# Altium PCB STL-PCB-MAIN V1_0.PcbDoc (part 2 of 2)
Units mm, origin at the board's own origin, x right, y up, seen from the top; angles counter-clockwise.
Board outline 48 x 35.2 mm, 4 copper layers (Top Layer, Int1 (GND), Int4 (PWR), Bottom Layer), stack 0.969 mm thick; 79 components, 63 nets, 420 pads, 232 vias.
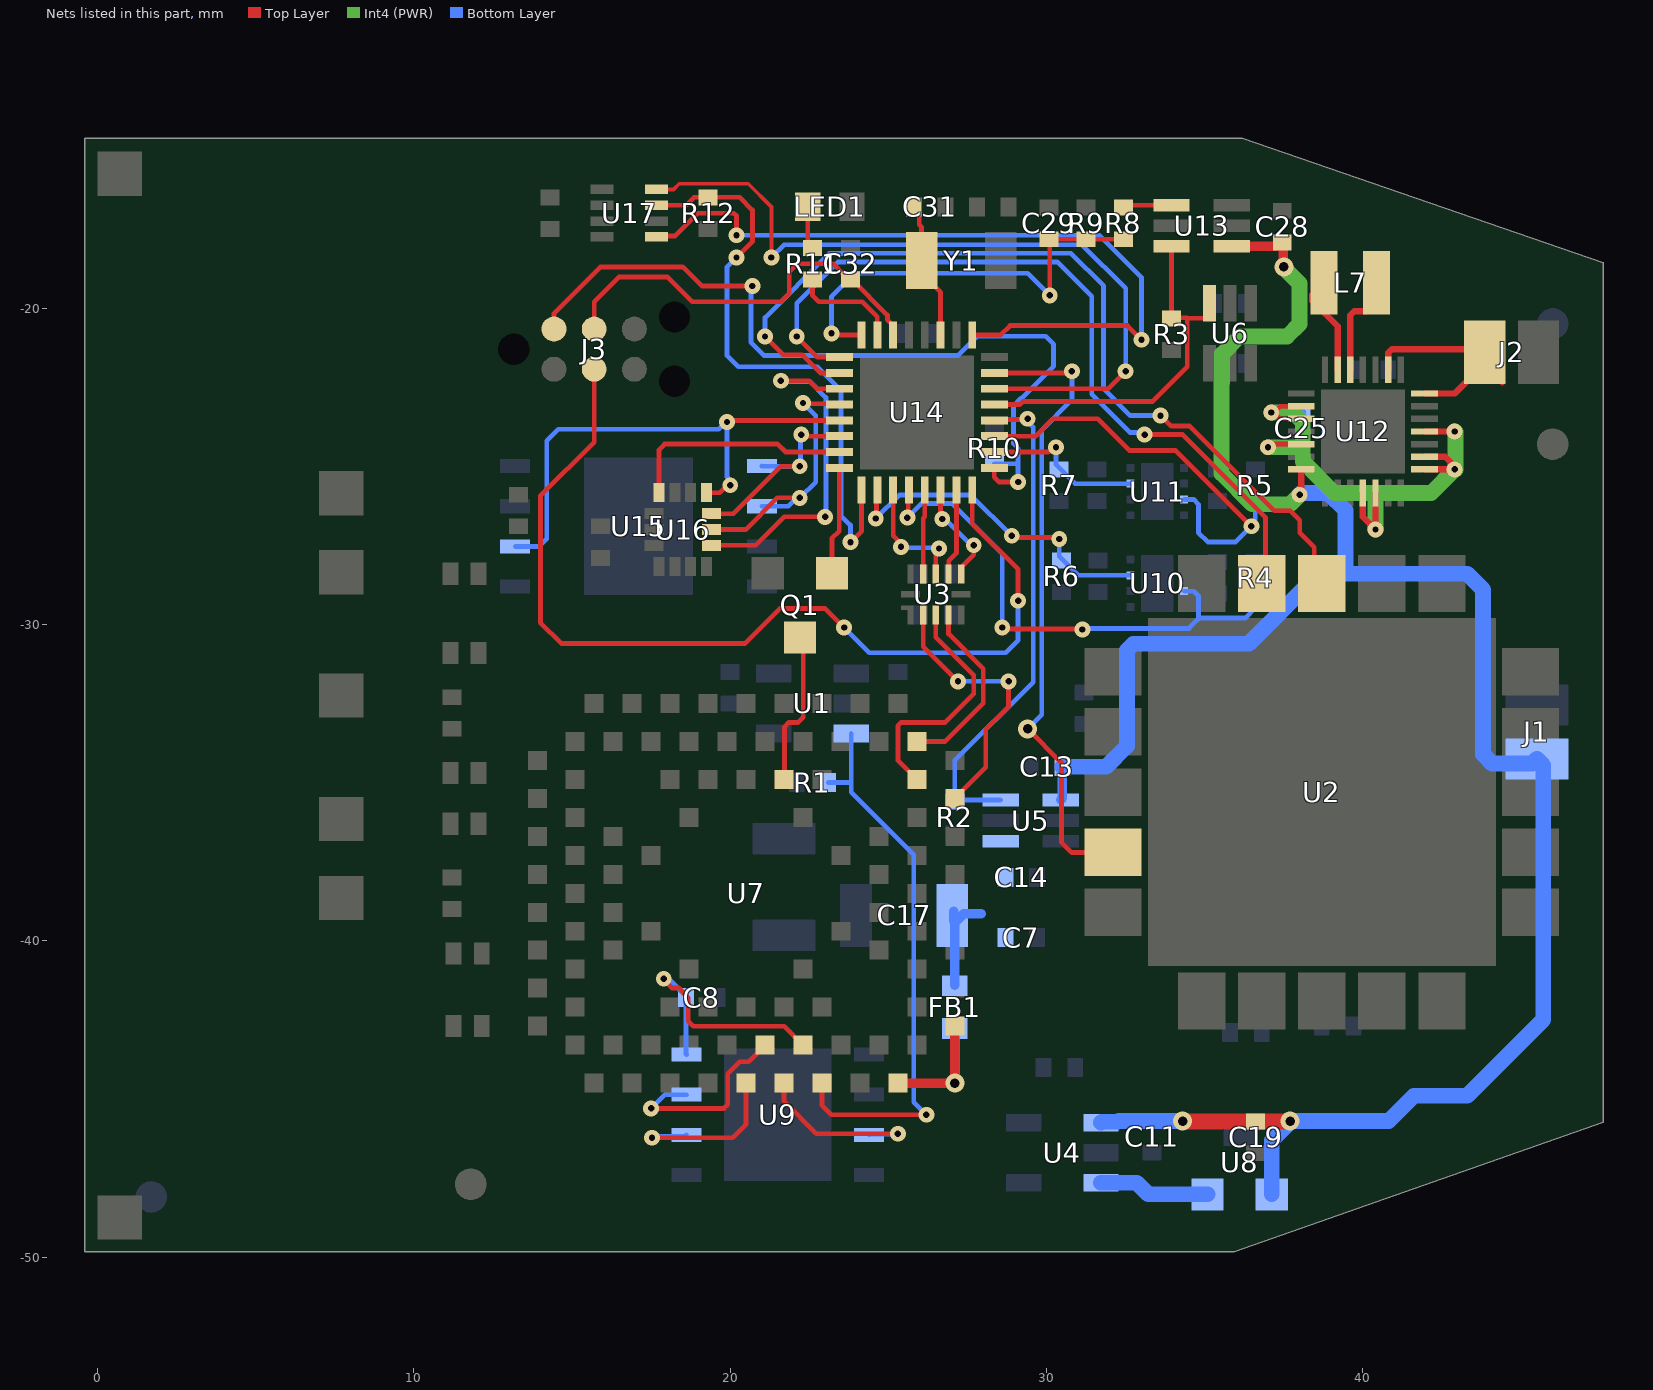
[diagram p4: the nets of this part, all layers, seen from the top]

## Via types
v1: diameter 0.6, hole 0.3, Top Layer to Bottom Layer, 120 vias
v2: diameter 0.5, hole 0.2, Top Layer to Bottom Layer, 112 vias

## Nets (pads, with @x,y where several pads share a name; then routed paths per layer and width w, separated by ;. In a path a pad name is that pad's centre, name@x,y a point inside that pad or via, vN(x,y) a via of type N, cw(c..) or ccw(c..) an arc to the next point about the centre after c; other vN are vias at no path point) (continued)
NetC31_1: C31.1 U14.3 Y1.1 | length 4.4
  Top Layer w0.15: C31.1@25.8,-16.8 25.975,-16.975 25.975,-17.363 26.05,-17.438 Y1.1@26.05,-18.5 26.05,-18.9 26.65,-19.5 U14.3@26.65,-20.85
NetFB1_1: FB1.1 U7.AA3 U7.W1 | length 5.3
  Top Layer w0.3: U7.W1@25.3,-44.5 v1(27.1,-44.5) U7.AA3@27.1,-42.7
  Bottom Layer w0.3: v1(27.1,-44.5) FB1.1@27.1,-42.775
NetJ2_1: J2.1 U12.2 U12.28 | length 7.6
  Top Layer w0.2: U12.2@40.8,-21.95 40.8,-21.417 40.917,-21.3 43.75,-21.3 J2.1@43.85,-21.4 43.85,-21.75 42.9,-22.7 U12.28@41.95,-22.7 ; J2.1@43.583,-21.4 43.892,-21.708 43.892,-21.842 J2.1@44.4,-22.35
NetL7_1: L7.1 U12.6 | length 3.2
  Top Layer w0.2: L7.1@38.775,-19.2 38.4,-19.575 38.4,-19.775 39.2,-20.575 U12.6@39.2,-21.95
NetL7_2: L7.2 U12.5 | length 3.3
  Top Layer w0.2: U12.5@39.6,-21.95 39.6,-20.225 39.725,-20.1 40.1,-20.1 40.425,-19.775 L7.2@40.425,-19.2
NetLED1_2: LED1.2 R11.1 | length 1.4
  Top Layer w0.15: LED1.2@22.45,-16.8 22.45,-17.95 R11.1@22.6,-18.1
NetQ1_1: Q1.1 U14.16 | length 3.4
  Top Layer w0.15: Q1.1@23.216,-28.384 23.216,-27.284 23.45,-27.05 U14.16@23.45,-25.05
NetQ1_3: Q1.3 U7.N16 | length 5
  Top Layer w0.15: U7.N16@21.7,-34.9 21.718,-34.882 21.718,-33.238 21.856,-33.1 22.144,-33.1 22.312,-32.932 22.312,-30.528 Q1.3@22.2,-30.416
NetR1_2: R1.2 U1.3 U7.R1 | length 17.9
  Top Layer w0.15: U7.R1@22.9,-44.5 22.9,-45.2 23.2,-45.5 v2(26.2,-45.5)
  Bottom Layer w0.15: R1.2@23.1,-35 23.822,-35 ; U1.3@23.822,-33.45 23.822,-35 ; v2(26.2,-45.5) 25.8,-45.1 25.8,-37.285 23.822,-35.307 23.822,-35
NetR2_2: R2.2 U5.3 U14.28 | length 15.7
  Top Layer w0.15: U14.28@28.35,-23.55 28.375,-23.525 29.375,-23.525 v2(29.4,-23.5)
  Bottom Layer w0.15: U5.3@28.55,-35.55 27.15,-35.55 R2.2@27.1,-35.6 27.1,-34.3 29.575,-31.825 29.575,-23.763 29.4,-23.588 v2(29.4,-23.5)
NetR4_1: R4.1 U10.3 U14.20 | length 17.1
  Top Layer w0.15: v2(25.6,-26.625) 25.625,-26.6 25.625,-25.775 U14.20@25.65,-25.75 ; v2(28.6,-30.1) 28.645,-30.145 31.118,-30.145 v2(31.132,-30.159)
  Bottom Layer w0.15: v2(25.6,-26.625) 26.044,-26.181 27.018,-26.181 28.6,-27.763 v2(28.6,-30.1) ; v2(31.132,-30.159) 31.163,-30.128 34.5,-30.128 34.8,-29.828 34.8,-29.1 34.65,-28.95 U10.3@34.35,-28.95 ; 34.8,-29.8 36.273,-29.8 36.6,-29.473 R4.1@36.6,-29.025
NetR5_1: R5.1 U11.3 U14.27 | length 14
  Top Layer w0.15: U14.27@28.35,-24.05 29.65,-24.05 30.2,-23.5 31.615,-23.5 32.615,-24.5 34.075,-24.5 v2(36.475,-26.9)
  Bottom Layer w0.15: U11.3@34.35,-26.05 34.65,-26.05 34.8,-26.2 34.8,-27.1 35.095,-27.395 35.98,-27.395 v2(36.475,-26.9) 36.475,-26.805 36.6,-26.68 R5.1@36.6,-26.1
NetR6_2: R6.2 U10.7 U14.18 | length 10.7
  Top Layer w0.15: v2(24.6,-26.65) 24.625,-26.625 24.625,-25.775 U14.18@24.65,-25.75 ; v2(28.9,-27.2) 28.95,-27.25 30.35,-27.25 v2(30.4,-27.3)
  Bottom Layer w0.15: v2(24.6,-26.65) 25.339,-25.911 27.611,-25.911 v2(28.9,-27.2) ; v2(30.4,-27.3) 30.4,-27.85 31,-28.45 U10.7@32.65,-28.45
NetR7_2: R7.2 U11.7 U14.26 | length 5.2
  Top Layer w0.15: U14.26@28.35,-24.55 30.055,-24.55 30.205,-24.4 v2(30.3,-24.4)
  Bottom Layer w0.15: v2(30.3,-24.4) 30.3,-24.95 30.9,-25.55 U11.7@32.65,-25.55
NetR8_2: R8.2 U13.1 | length 1.6
  Top Layer w0.15: R8.2@32.425,-16.825 32.5,-16.75 U13.1@33.95,-16.75
NetR11_2: R11.2 U14.7 | length 3.4
  Top Layer w0.15: R11.2@22.6,-19.1 22.6,-19.6 22.8,-19.8 24.168,-19.8 24.65,-20.282 U14.7@24.65,-20.85
NetR12_1: R12.1 U14.17 U17.7 | length 19
  Top Layer w0.15: U17.7@17.67,-16.75 18.606,-16.75 18.856,-16.5 R12.1@19.3,-16.5 20.299,-16.5 20.7,-16.901 20.7,-17.9 v2(20.2,-18.4) ; v2(23.8,-27.4) 24.15,-27.05 U14.17@24.15,-25.75
  Bottom Layer w0.15: v2(20.2,-18.4) 19.9,-18.7 19.9,-21.5 20.255,-21.855 22.755,-21.855 23.5,-22.6 23.5,-26.561 23.8,-26.861 v2(23.8,-27.4)
NetU2_13: U2.13 U14.10 | length 28.9
  Top Layer w0.15: v2(21.1,-20.9) 21.675,-21.475 22.275,-21.475 22.85,-22.05 U14.10@23.45,-22.05 ; v2(33.6,-23.4) 33.612,-23.4 33.942,-23.73 34.527,-23.73 37.202,-26.405 37.705,-26.405 38.005,-26.705 38.005,-27.105 38.463,-27.563 38.463,-28.463 U2.13@38.7,-28.7
  Bottom Layer w0.15: v2(21.1,-20.9) 21.1,-20.3 23.13,-18.27 30.77,-18.27 31.8,-19.3 31.8,-22.556 32.644,-23.4 v2(33.6,-23.4)
NetU2_14: U2.14 U14.9 | length 25.3
  Top Layer w0.15: v2(22.1,-20.9) 22.75,-21.55 U14.9@23.45,-21.55 ; v2(33.1,-24) 34.3,-24 36.92,-26.62 36.92,-28.58 U2.14@36.8,-28.7
  Bottom Layer w0.15: v2(22.1,-20.9) 22.1,-19.85 23.41,-18.54 30.34,-18.54 31.428,-19.628 31.428,-22.728 32.633,-23.933 33.033,-23.933 v2(33.1,-24)
NetU2_19: U2.19 U14.31 | length 20.2
  Top Layer w0.15: U14.31@28.35,-22.05 30.75,-22.05 v2(30.8,-22) ; v1(29.4,-33.3) 30.468,-34.368 30.468,-36.886 30.794,-37.212 32.088,-37.212 U2.19@32.1,-37.2
  Bottom Layer w0.15: v1(29.4,-33.3) 29.845,-32.855 29.845,-23.855 30.8,-22.9 v2(30.8,-22)
NetU3_7: U3.7 U14.22 | length 3.3
  Top Layer w0.15: U14.22@26.65,-25.75 26.65,-26.611 v2(26.705,-26.666) ; U3.7@27.3,-28.4 27.3,-28.2 27.7,-27.8 v2(27.7,-27.5)
  Bottom Layer w0.15: v2(26.705,-26.666) 26.786,-26.666 27.619,-27.5 v2(27.7,-27.5)
NetU3_8: U3.8 U14.23 | length 2.8
  Top Layer w0.15: U3.8@26.9,-28.4 26.909,-28.391 26.909,-27.991 27.15,-27.75 U14.23@27.15,-25.75
NetU3_9: U3.9 U14.19 | length 4
  Top Layer w0.15: U14.19@25.15,-25.75 25.15,-27.205 25.4,-27.455 v2(25.4,-27.55) ; U3.9@26.5,-28.4 26.5,-27.795 26.6,-27.695 v2(26.6,-27.6)
  Bottom Layer w0.15: v2(25.4,-27.55) 25.425,-27.575 26.575,-27.575 v2(26.6,-27.6)
NetU3_10: U3.10 U14.21 | length 2.7
  Top Layer w0.15: U3.10@26.1,-28.4 26.1,-26.65 26.15,-26.6 U14.21@26.15,-25.75
NetU4_3: U4.3 U8.2 | length 3.5
  Bottom Layer w0.5: U4.3@31.722,-47.65 32.85,-47.65 33.216,-48.016 U8.2@35.084,-48.016
NetU14_1: U14.1 U17.5 | length 24.5
  Top Layer w0.15: U17.5@17.67,-17.75 17.701,-17.719 18.255,-17.719 18.974,-17 20.112,-17 20.2,-17.088 v2(20.2,-17.7) ; U14.1@27.65,-20.85 28.55,-20.85 28.845,-20.555 32.555,-20.555 v2(33,-21)
  Bottom Layer w0.15: v2(20.2,-17.7) 31.671,-17.7 33,-19.029 v2(33,-21)
NetU14_11: U14.11 U16.12 | length 11.3
  Top Layer w0.15: U16.12@19.412,-27.5 20.81,-27.5 21.71,-26.6 v2(23,-26.6) ; v2(21.6,-22.3) 22.494,-22.3 22.744,-22.55 U14.11@23.45,-22.55
  Bottom Layer w0.15: v2(21.6,-22.3) 21.621,-22.321 22.515,-22.321 23.025,-22.831 23.025,-26.575 v2(23,-26.6)
NetU14_15: U14.15 U16.4 | length 7.2
  Top Layer w0.15: U16.4@17.75,-25.837 17.75,-24.476 17.926,-24.3 21.5,-24.3 21.75,-24.55 U14.15@23.45,-24.55
NetU14_30: U14.30 U17.8 | length 24.5
  Top Layer w0.12: U17.8@17.67,-16.25 18.208,-16.25 18.388,-16.07 20.57,-16.07 21.3,-16.8 v2(21.3,-18.4)
  Top Layer w0.15: U14.30@28.35,-22.55 31.95,-22.55 v2(32.5,-22)
  Bottom Layer w0.15: v2(21.3,-18.4) 21.7,-18 31.12,-18 32.5,-19.38 v2(32.5,-22)
NRST: C32.1 J3.4 U14.6 | length 13.3
  Top Layer w0.15: J3.4@15.7,-20.865 15.7,-19.8 16.48,-19.02 18.02,-19.02 18.8,-19.8 21.6,-19.8 21.862,-19.538 21.862,-18.85 22.112,-18.6 23.25,-18.6 23.75,-19.1 C32.1@23.8,-19.1 23.85,-19.1 24.97,-20.22 24.97,-20.37 25.15,-20.55 U14.6@25.15,-20.85
ON_OFF: R3.2 U6.3 U13.3 U14.29 | length 12
  Top Layer w0.15: U14.29@28.35,-23.05 29.152,-23.05 29.248,-22.955 33.345,-22.955 34.445,-21.855 34.445,-20.305 R3.2@33.95,-20.305 ; R3.2@33.95,-20.325 R3.2@33.95,-20.305 ; U13.3@33.95,-18.05 R3.2@33.95,-20.305 ; 34.445,-20.325 35.025,-20.325 35.15,-20.2 U6.3@35.15,-19.85
RTS1V8: U3.4 U7.Y18 | length 5.9
  Top Layer w0.15: U7.Y18@25.9,-33.7 26.8,-33.7 28,-32.5 28,-31.4 26.9,-30.3 U3.4@26.9,-29.7
RX1V8: U3.2 U7.AA15 | length 8.6
  Top Layer w0.15: U3.2@26.1,-29.7 26.1,-30.7 v2(27.2,-31.8) ; U7.AA15@27.1,-35.5 28.079,-34.521 28.079,-33.321 28.8,-32.6 v2(28.8,-31.8)
  Bottom Layer w0.15: v2(27.2,-31.8) v2(28.8,-31.8)
SIMCLK: U7.L1 U9.6 | length 5.6
  Top Layer w0.15: v2(17.525,-46.225) 20.075,-46.225 20.5,-45.8 U7.L1@20.5,-44.5
  Bottom Layer w0.15: v2(17.525,-46.225) 17.57,-46.18 18.57,-46.18 U9.6@18.615,-46.135
SIMDAT: U7.N1 U9.3 | length 5.5
  Top Layer w0.15: U7.N1@21.7,-44.5 21.7,-45.075 22.725,-46.1 v2(25.3,-46.1)
  Bottom Layer w0.15: U9.3@24.385,-46.135 24.403,-46.117 25.282,-46.117 v2(25.3,-46.1)
SIMRST: U7.M2 U9.7 | length 6.3
  Top Layer w0.15: v2(17.5,-45.3) 19.8,-45.3 19.922,-45.178 19.922,-44.202 20.302,-43.822 20.578,-43.822 U7.M2@21.1,-43.3
  Bottom Layer w0.15: v2(17.5,-45.3) 17.935,-44.865 U9.7@18.615,-44.865
SIMVCC: C8.2 U7.P2 U9.8 | length 8.5
  Top Layer w0.15: v2(17.9,-41.2) 17.9,-41.239 18.154,-41.493 18.369,-41.493 18.675,-41.799 18.675,-42.543 18.832,-42.7 21.7,-42.7 U7.P2@22.3,-43.3
  Bottom Layer w0.15: v2(17.9,-41.2) 17.967,-41.267 18.117,-41.267 18.6,-41.75 C8.2@18.6,-41.8 18.6,-43.58 U9.8@18.615,-43.595
SPI_MISO: U14.13 U15.2 U16.1 | length 16.6
  Top Layer w0.15: U16.1@19.25,-25.837 19.668,-25.837 19.905,-25.6 v2(20,-25.6) ; v2(19.9,-23.6) 19.945,-23.555 23.445,-23.555 U14.13@23.45,-23.55
  Bottom Layer w0.15: U15.2@13.2,-27.535 13.965,-27.535 14.2,-27.3 14.2,-24.2 14.571,-23.829 19.637,-23.829 19.867,-23.6 v2(19.9,-23.6) 19.9,-25.337 19.933,-25.37 19.933,-25.533 v2(20,-25.6)
SPI_MOSI: U14.14 U15.5 U16.14 | length 6.9
  Top Layer w0.15: U16.14@19.412,-26.5 20.102,-26.5 21.602,-25 v2(22.2,-25) ; v2(22.245,-24) 22.295,-24.05 U14.14@23.45,-24.05
  Bottom Layer w0.15: U15.5@21,-24.995 21.005,-25 v2(22.2,-25) 22.223,-24.977 22.223,-24.068 22.2,-24.045 v2(22.245,-24)
SPI_SCK: U14.12 U15.6 U16.13 | length 9.1
  Top Layer w0.15: U16.13@19.412,-27 20.49,-27 21.49,-26 v2(22.2,-26) ; v2(22.3,-23) 22.325,-23.025 23.425,-23.025 U14.12@23.45,-23.05
  Bottom Layer w0.15: U15.6@21,-26.265 21.84,-26.265 22.105,-26 v2(22.2,-26) 22.7,-25.5 22.7,-23.4 v2(22.3,-23)
SWDCLK: J3.2 R10.1 U14.25 | length 26.6
  Top Layer w0.15: J3.2@14.43,-20.865 14.43,-20.17 15.9,-18.7 18.5,-18.7 19.1,-19.3 v2(20.7,-19.3) ; U14.25@28.35,-25.05 28.35,-25.35 28.5,-25.5 v2(29.1,-25.5)
  Bottom Layer w0.15: v2(20.7,-19.3) 20.655,-19.345 20.655,-21.084 21.071,-21.5 27.2,-21.5 27.812,-20.887 29.968,-20.887 30.222,-21.142 30.222,-21.837 29.209,-22.85 29.185,-22.85 28.955,-23.081 28.955,-24.288 29.1,-24.433 29.1,-24.966 ; R10.1@28.35,-24.925 29.059,-24.925 29.1,-24.966 ; v2(29.1,-25.5) 29.1,-24.966
SWDIO: J3.3 U14.24 | length 30.4
  Top Layer w0.15: J3.3@15.7,-22.135 15.7,-24.236 14,-25.936 14,-29.945 14.655,-30.6 20.471,-30.6 21.571,-29.5 23,-29.5 v2(23.6,-30.1) ; U14.24@27.65,-25.75 27.65,-26.813 29.1,-28.263 v2(29.1,-29.25)
  Bottom Layer w0.15: v2(23.6,-30.1) 24.395,-30.895 28.705,-30.895 29.1,-30.5 v2(29.1,-29.25)
TX1V8: U3.3 U7.Y16 | length 7.8
  Top Layer w0.15: U7.Y16@25.9,-34.9 25.3,-34.3 25.3,-33.2 25.4,-33.1 26.8,-33.1 27.7,-32.2 27.7,-31.6 26.5,-30.4 ; 26.5,-30.399 U3.3@26.5,-29.7
VBAT: C11.2 C13.2 C19.2 C28.2 J1.1 U4.1 U5.4 U8.1 U12.14 U13.4 | length 70.6
  Top Layer w0.2: v2(38,-25.9) 38.05,-25.85 U12.14@38.05,-25.1
  Top Layer w0.3: U13.4@35.85,-18.05 C28.2@37.275,-18.05 ; C28.2@37.45,-17.925 37.475,-17.95 37.475,-18.675 v1(37.5,-18.7)
  Top Layer w0.5: v1(34.3,-45.7) 34.318,-45.718 C19.2@36.608,-45.718 37.682,-45.718 v1(37.7,-45.7)
  Int4 (PWR) w0.5: v1(37.5,-18.7) 37.5,-18.727 38,-19.227 38,-20.5 37.6,-20.9 36.1,-20.9 35.55,-21.45 35.55,-22.354 35.53,-22.374 35.53,-25.23 36.5,-26.2 37.7,-26.2 v2(38,-25.9)
  Bottom Layer w0.3: U5.4@30.45,-35.55 30.5,-35.5 C13.2@30.5,-34.5
  Bottom Layer w0.5: C13.2@30.5,-34.5 31.886,-34.5 32.542,-33.844 32.542,-30.82 32.75,-30.612 36.39,-30.612 38.603,-28.4 39.45,-28.4 ; U4.1@31.722,-45.75 31.751,-45.721 32.259,-45.721 32.279,-45.7 C11.2@33.329,-45.7 v1(34.3,-45.7) ; U8.1@37.116,-48.016 37.116,-46.311 37.7,-45.727 v1(37.7,-45.7) 40.814,-45.7 41.614,-44.9 43.3,-44.9 45.7,-42.5 45.7,-34.45 J1.1@45.5,-34.25 45.35,-34.4 44.093,-34.4 43.8,-34.107 43.8,-28.906 43.294,-28.4 39.45,-28.4 ; v2(38,-25.9) 38.05,-25.85 38.9,-25.85 39.45,-26.4 39.45,-28.4
VBAT_MEAS: C29.2 R8.1 R9.2 U14.8 | length 13.8
  Top Layer w0.15: v2(23.2,-20.8) 23.25,-20.85 U14.8@24.15,-20.85 ; v2(30.1,-19.6) 30.1,-17.85 C29.2@30.075,-17.825 R9.2@31.25,-17.825 R8.1@32.425,-17.825
  Bottom Layer w0.15: v2(23.2,-20.8) 23.2,-19.65 23.95,-18.9 29.4,-18.9 v2(30.1,-19.6)
VINT: C25.2 U12.9 U12.10 U12.12 U12.18 U12.19 U12.22 U12.23 U12.25 | length 20.7
  Top Layer w0.15: v2(37.1,-23.3) v2@37.195,-23.3 ; v2@37.195,-24.3 U12.12@38.05,-24.3 ; U12.10@38.05,-23.5 37.395,-23.5 v2@37.195,-23.3 ; U12.9@38.05,-23.1 37.395,-23.1 v2@37.195,-23.3
  Top Layer w0.2: U12.18@40,-25.85 40,-26.6 v2(40.4,-27) U12.19@40.4,-25.85 ; U12.22@41.95,-25.1 v2(42.9,-25.1) 42.843,-25.043 42.843,-24.943 42.6,-24.7 U12.23@41.95,-24.7 ; U12.25@41.95,-23.9 v2(42.9,-23.9)
  Int4 (PWR) w0.5: v2(37,-24.4) 38.1,-24.4 ; v2(37.1,-23.3) 37.8,-23.3 38.1,-23.6 38.1,-24.4 ; v2(40.4,-27) 40.4,-25.85 ; v2(42.9,-25.1) 42.15,-25.85 40.4,-25.85 ; v2(42.9,-23.9) 42.922,-23.922 v2@42.922,-25.1 ; 38.1,-24.4 38.1,-24.848 39.102,-25.85 40.4,-25.85
  Bottom Layer w0.3: v2(37.1,-23.3) C25.2@38.05,-23.3
VLTE: C7.2 C14.2 C17.2 FB1.2 U5.1 | length 3.3
  Bottom Layer w0.3: C17.2@27.064,-39.069 27.064,-39.388 27.076,-39.4 C17.2@27.1,-39.424 ; FB1.2@27.1,-41.4 C17.2@27.1,-39.424 ; 27.938,-39.15 27.374,-39.15 C17.2@27.1,-39.424
pads on no net: ANT1.1 ANT1.2 ANT1.6 ANT1.7 J3.5 J3.7 J3.8 J3.9 U1.4 U2.7 U2.8 U2.9 U2.12 U2.18 U4.4 U5.6 U6.6 U7.A11 U7.A15 U7.AA5 U7.AA7 U7.AA9 U7.AA11 U7.AA13 U7.B2 U7.B8 U7.B18 U7.C1 U7.D2 U7.D7 U7.D9 U7.D11 U7.D13 U7.E1 U7.E19 U7.F2 U7.G1 U7.G4 U7.G16 U7.H2 U7.H18 U7.J1 U7.J4 U7.J16 U7.K2 U7.L4 U7.L16 U7.L19 U7.P18 U7.R4 U7.R16 U7.R19 U7.T2 U7.T18 U7.U19 U7.V7 U7.V9 U7.V11 U7.V13 U7.V18 U7.Y6 U7.Y8 U7.Y10 U7.Y12 U7.Y14 U9.2 U9.4 U9.5 U10.4 U11.4 U12.1 U12.15 U12.16 U12.17 U12.26 U13.6 U16.9 U16.10 U16.11 U17.3 U17.6

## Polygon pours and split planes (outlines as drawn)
GND on Int1 (GND) "NONET_L-01_P-001" (solid, remove dead copper, pour order 0): 12,-12.9 52.5,-12.9 52.5,-49.2 49.9,-51.8 49.8,-51.7 12,-51.7
GND on Int4 (PWR) "NONET_L-01_P-001" (solid, remove dead copper, pour order 1): 12.4,-12.7 51.9,-12.7 51.9,-47 44.6,-54.3 42.8,-52.5 12.4,-52.5
GND on Top Layer "NONET_L-01_P-001" (solid, remove dead copper, pour order 2): 12,-11.4 50,-11.4 52.9,-14.3 52.7,-14.5 52.7,-49 48.6,-53.1 12,-53.1
GND on Bottom Layer "NONET_L-01_P-001" (solid, remove dead copper, pour order 3): 12.1,-11.7 46.5,-11.7 52.1,-17.3 52.1,-44.2 44.7,-51.6 12.1,-51.6

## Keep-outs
Top Layer:
  circle w0.1: c11.8,-47.7 r1.204
  circle w0.1: c46,-24.3 r1.105
  region: 11.577,-14.625 11.577,-15.7 47.9,-15.7 47.9,-14.625
  region: 8.7,-48.7 8.7,-49.75 49.2,-49.75 49.2,-48.7
Bottom Layer:
  circle w0.1: c1.7,-48.1 r1.105
  circle w0.1: c46,-20.5 r1.105
Keep-Out Layer:
  lines w1: -0.4,-49.825 -0.4,-14.625 36.188,-14.625 47.719,-18.603 47.719,-45.696 35.933,-49.825 -0.4,-49.825

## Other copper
Top Layer:
  rectangle net +1V8: 24.125,-30.8 25.375,-28.95
  rectangle net GND: 44.9,-22.8 46.7,-20
  rectangle net NetJ2_1: 42.667,-22.8 44.5,-20
  pour cut-out: 13.407,-20.471 18.148,-20.471 18.148,-22.529 13.407,-22.529
  pour cut-out: 12.594,-26.835 12.594,-43.4 10.5,-43.4 10.5,-26.782
  text "FACE GRAVURE REFERENCE" at 17.543,-128.273 h1.78
Int1 (GND):
  text "FACE GRAVURE INTERNE 1" at 14.693,-128.523 h1.78
Int4 (PWR):
  text "FACE GRAVURE INTERNE 4" at 59.443,-128.423 h1.78
Bottom Layer:
  rectangle net VBAT: 44.5,-36.3 46.8,-33.6
  rectangle net GND: 44.5,-33.2 46.8,-30.5
  rectangle net VLTE: 26.676,-40.2 28.95,-38.2
  region net VLTE: 28.999,-36.65 27.975,-36.65 27.975,-39.312 28.999,-39.312
  pour cut-out: 10.553,-26.835 12.594,-26.835 12.594,-43.4 10.525,-43.4 10.525,-26.807
  text "FACE GRAVURE VERSO" at 59.443,-128.423 h1.78

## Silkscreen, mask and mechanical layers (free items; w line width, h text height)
Top Overlay:
  text "PV" at 43.1,-19.8 h1
  text "GND" at 44.7,-19.788 h1
  text "STL-PCB-MAIN V1_0" at 13.784,-49.36 h1.5
  text "FACE SERIGRAPHIE REFERENCE" at 18.243,-128.073 h1.78
Bottom Overlay:
  text "STL-PCB-MAIN V1_0" at 35.3,-16.735 h1.5
  text "GND" at 46.2,-31.288 h1
  text "+VBAT" at 46.6,-36.3 h1
  text "FACE SERIGRAPHIE VERSO" at 62.043,-128.223 h1.78
Top Paste:
  text "FACE BRASAGE REFERENCE" at 14.943,-128.023 h1.78
Bottom Paste:
  text "FACE BRASAGE VERSO" at 59.043,-128.423 h1.78
Top Solder:
  text "FACE VERNIS EPARGNE REFERENCE" at 7.643,-128.123 h1.78
Bottom Solder:
  text "FACE VERNIS EPARGNE VERSO" at 64.943,-128.323 h1.78
Top Mechanical 1/Mechanical 2:
  circle w0.013: c37.362,18.974 r0.495
  circle w0.013: c37.362,21.006 r0.495
  circle w0.013: c62.447,8.447 r0.5
  circle w0.013: c67.547,13.547 r0.5
  circle w0.013: c57.997,10.997 r1
  circle w0.013: c64.997,4.997 r0.375
  circle w0.013: c62.447,13.547 r0.5
  circle w0.013: c67.547,8.447 r0.5
  circle w0.013: c34.797,10.997 r0.5
  circle w0.013: c42.442,19.99 r0.495
  circle w0.013: c32.297,10.997 r0.4
  circle w0.013: c71.997,10.997 r1
  circle w0.013: c67.547,8.447 r0.5
  circle w0.013: c67.547,8.447 r0.5
  circle w0.013: c37.362,21.006 r0.495
  circle w0.013: c37.362,18.974 r0.495
  circle w0.013: c42.442,19.99 r0.495
  circle w0.013: c64.997,4.997 r0.375
  circle w0.013: c62.447,8.447 r0.5
  circle w0.013: c62.447,8.447 r0.5
  circle w0.013: c57.997,10.997 r1
  circle w0.013: c57.997,10.997 r1
  circle w0.013: c62.447,13.547 r0.5
  circle w0.013: c62.447,13.547 r0.5
  circle w0.013: c67.547,13.547 r0.5
  circle w0.013: c67.547,13.547 r0.5
  lines w0.013: 0,0 0,36.322 ; 0,0 0,36.322 ; 0,0 0,36.322 ; 0,36.322 10.597,36.322 ; 0,36.322 10.597,36.322 ; 0,36.322 10.597,36.322 ; 50.372,21.997 cw(c49.997,21.997) 49.622,21.997 ccw(c49.997,21.997) 50.372,21.997 ; 50.372,21.997 74.997,21.997 ; 50.372,21.997 74.997,21.997 ; 70.988,10.997 71.023,10.736 ; 70.988,10.997 71.023,11.258 ; 70.988,10.997 71.023,10.736 ; 70.988,10.997 71.023,11.258 ; 71.023,10.736 71.124,10.493 ; 71.023,10.736 71.124,10.493 ; 71.023,11.258 71.124,11.501 ; 71.023,11.258 71.124,11.501 ; 71.124,10.493 71.284,10.284 ; 71.124,10.493 71.284,10.284 ; 71.124,11.501 71.284,11.71 ; 71.124,11.501 71.284,11.71 ; 71.284,10.284 71.493,10.123 ; 71.284,10.284 71.493,10.123 ; 71.284,11.71 71.493,11.87 ; 71.284,11.71 71.493,11.87 ; 71.493,10.123 71.736,10.023 ; 71.493,10.123 71.736,10.023 ; 71.493,11.87 71.736,11.971 ; 71.493,11.87 71.736,11.971 ; 71.736,10.023 71.997,9.988 ; 71.736,10.023 71.997,9.988 ; 71.736,11.971 71.997,12.006 ; 71.736,11.971 71.997,12.006 ; 71.997,9.988 72.258,10.023 ; 71.997,9.988 72.258,10.023 ; 71.997,12.006 72.258,11.971 ; 71.997,12.006 72.258,11.971 ; 72.258,10.023 72.501,10.123 ; 72.258,10.023 72.501,10.123 ; 72.258,11.971 72.501,11.87 ; 72.258,11.971 72.501,11.87 ; 72.501,10.123 72.71,10.284 ; 72.501,10.123 72.71,10.284 ; 72.501,11.87 72.71,11.71 ; 72.501,11.87 72.71,11.71 ; 72.71,10.284 72.871,10.493 ; 72.71,10.284 72.871,10.493 ; 72.71,11.71 72.871,11.501 ; 72.71,11.71 72.871,11.501 ; 72.871,10.493 72.971,10.736 ; 72.871,10.493 72.971,10.736 ; 72.871,11.501 72.971,11.258 ; 72.871,11.501 72.971,11.258 ; 72.971,10.736 73.006,10.997 ; 72.971,10.736 73.006,10.997 ; 72.971,11.258 73.006,10.997 ; 72.971,11.258 73.006,10.997 ; 74.997,-0.003 74.997,21.997 ; 74.997,-0.003 74.997,21.997 ; 74.997,-0.003 74.997,21.997
Top Equip top/Equip bot:
  text "L7" at 39.15,-19.45 h0.6
  text "U3" at 26.05,-29.35 h0.6
  text "PLAN EQUIPEMENT REFERENCE" at 22.643,-128.473 h2
Bottom Equip top/Equip bot:
  text "U11" at 34.05,-26.15 h0.6
  text "U15" at 17.85,-27.55 h0.6
  text "U10" at 34.05,-29.05 h0.6
  text "U9" at 22.25,-46.05 h0.8
  text "PLAN EQUIPEMENT VERSO" at 71.118,-128.773 h2
Drill Drawing:
  circle w0.254: c-18.187,40.701 r0.847
  lines w0.1: 10.5,-17.3 10.531,-17.286 13.2,-10.4 ; 9.086,-22.65 12.197,-22.65 12.197,-16.4 9.086,-16.4 9.086,-22.65
  lines w0.254: -19.034,32.234 -17.34,32.234 -17.34,33.927 -19.034,33.927 -19.034,32.234 ; -19.034,37.737 -17.34,37.737 -18.187,36.044 -19.034,37.737
  lines w0.381: -20.552,31.091 106.16,31.091 ; -20.552,42.521 106.16,42.521 ; -6.56,27.281 -6.56,46.331 ; -1.551,67.94 8.86,67.94 32.476,67.94 47.712,67.94 64.218,67.94 78.693,67.94 ; -1.551,70.988 8.86,70.988 32.476,70.988 47.712,70.988 64.218,70.988 78.693,70.988 ; -1.551,74.036 8.86,74.036 32.476,74.036 47.712,74.036 64.218,74.036 78.693,74.036 ; -1.551,77.084 8.86,77.084 32.476,77.084 47.712,77.084 64.218,77.084 78.693,77.084 ; -1.551,80.132 8.86,80.132 32.476,80.132 47.712,80.132 64.218,80.132 78.693,80.132 ; -1.551,83.18 8.86,83.18 32.476,83.18 47.712,83.18 64.218,83.18 78.693,83.18 ; -1.551,86.228 8.86,86.228 32.476,86.228 47.712,86.228 64.218,86.228 78.693,86.228 ; -1.551,89.276 8.86,89.276 32.476,89.276 47.712,89.276 64.218,89.276 78.693,89.276 ; -1.551,92.324 8.86,92.324 32.476,92.324 47.712,92.324 64.218,92.324 78.693,92.324 ; -1.551,95.372 8.86,95.372 32.476,95.372 47.712,95.372 64.218,95.372 78.693,95.372 ; -1.551,98.42 78.693,98.42 ; 8.676,27.281 8.676,46.331 ; 8.86,101.468 8.86,64.892 ; 32.476,101.468 32.476,64.892 ; 36.862,27.281 36.862,46.331 ; 47.712,101.468 47.712,64.892 ; 49.711,27.281 49.711,46.331 ; 64.218,101.468 64.218,64.892 ; 68.35,27.281 68.35,46.331 ; 83.332,27.281 83.332,46.331 ; 8.86,64.892 32.476,64.892 ; 8.86,64.892 -1.551,64.892 -1.551,101.468 78.693,101.468 78.693,64.892 64.218,64.892 ; 32.476,64.892 47.712,64.892 ; 47.712,64.892 64.218,64.892 ; -20.552,27.281 106.16,27.281 106.16,46.331 -20.552,46.331 -20.552,27.281
  text "Layer" at 0.227,99.182 h1.52
  text "Name" at 10.638,99.182 h1.52
  text "Material" at 34.254,99.182 h1.52
  text "Thickness" at 49.49,99.182 h1.52
  text "Constant" at 65.996,99.182 h1.52
  text "Top Overlay" at 10.638,96.134 h1.52
  text "Top Solder" at 10.638,93.086 h1.52
  text "SM-001" at 34.254,93.086 h1.52
  text "0.025mm" at 49.49,93.086 h1.52
  text "4" at 65.996,93.086 h1.52
  text "1" at 0.227,90.038 h1.52
  text "Top Layer" at 10.638,90.038 h1.52
  text "CF-004" at 34.254,90.038 h1.52
  text "0.035mm" at 49.49,90.038 h1.52
  text "Dielectric 1" at 10.638,86.99 h1.52
  text "PP-021" at 34.254,86.99 h1.52
  text "0.180mm" at 49.49,86.99 h1.52
  text "4.7" at 65.996,86.99 h1.52
  text "2" at 0.227,83.942 h1.52
  text "Int1 (GND)" at 10.638,83.942 h1.52
  text "CF-004" at 34.254,83.942 h1.52
  text "0.015mm" at 49.49,83.942 h1.52
  text "Dielectric 2" at 10.638,80.894 h1.52
  text "Core-036" at 34.254,80.894 h1.52
  text "0.508mm" at 49.49,80.894 h1.52
  text "4.6" at 65.996,80.894 h1.52
  text "3" at 0.227,77.846 h1.52
  text "Int4 (PWR)" at 10.638,77.846 h1.52
  text "CF-004" at 34.254,77.846 h1.52
  text "0.015mm" at 49.49,77.846 h1.52
  text "Dielectric 3" at 10.638,74.798 h1.52
  text "PP-021" at 34.254,74.798 h1.52
  text "0.180mm" at 49.49,74.798 h1.52
  text "4.7" at 65.996,74.798 h1.52
  text "4" at 0.227,71.75 h1.52
  text "Bottom Layer" at 10.638,71.75 h1.52
  text "CF-004" at 34.254,71.75 h1.52
  text "0.035mm" at 49.49,71.75 h1.52
  text "Bottom Solder" at 10.638,68.702 h1.52
  text "SM-001" at 34.254,68.702 h1.52
  text "0.025mm" at 49.49,68.702 h1.52
  text "4" at 65.996,68.702 h1.52
  text "Bottom Overlay" at 10.638,65.654 h1.52
  text "Total board thickness:" at 0.227,62.606 h1.52
  text "1.020mm" at 49.49,62.606 h1.52
  text "Symbol" at -18.266,43.664 h1.83
  text "Count" at -5.417,43.664 h1.83
  text "Hole Size" at 9.819,43.664 h1.83
  text "Plated" at 38.005,43.664 h1.83
  text "Hole Type" at 50.854,43.664 h1.83
  text "Via/Pad" at 69.493,43.664 h1.83
  text "Description" at 84.475,43.664 h1.83
  text "112" at -5.417,39.854 h1.52
  text "0,200mm (7,87mil)" at 9.819,39.854 h1.52
  text "PTH" at 38.005,39.854 h1.52
  text "Round" at 50.854,39.854 h1.52
  text "Via" at 69.493,39.854 h1.52
  text "120" at -5.417,36.044 h1.52
  text "0,300mm (11,81mil)" at 9.819,36.044 h1.52
  text "PTH" at 38.005,36.044 h1.52
  text "Round" at 50.854,36.044 h1.52
  text "Via" at 69.493,36.044 h1.52
  text "3" at -5.417,32.234 h1.52
  text "0,991mm (39,02mil)" at 9.819,32.234 h1.52
  text "NPTH" at 38.005,32.234 h1.52
  text "Round" at 50.854,32.234 h1.52
  text "Pad" at 69.493,32.234 h1.52
  text "235 Total" at -5.417,28.424 h1.52
  text "MANUFACTURER MARKING AREA ON BOTTOM SOLDER" at 13.1,-10 h1.5
  text "PLAN DE PERCAGE" at 21.143,-128.323 h1.78
board:
  lines w0.1: 47.599,-18.562 36.188,-14.625 -0.4,-14.625 -0.4,-49.825 35.933,-49.825 47.6,-45.738 47.6,-18.565
specification ci:
  drawing of 299 lines, arcs and shapes, not listed
  text "FICHE TECHNIQUE (SELON NF C93-713)" at 11.143,112.527 h1.33
  text "SIMPLE FACE" at -36.857,107.527 h1.33
  text "BOUCHAGE DES VIAS(FILLED)" at 61.893,107.277 h1.33
  text "DOUBLE FACE TROUS METAL" at -36.857,104.027 h1.33
  text "PERCES" at 26.293,103.472 h1.33
  text "BOUCHAGE PATE PLUGING" at 47.143,101.277 h1.33
  text "DOUBLE FACE TROUS NON METAL" at -36.857,100.027 h1.33
  text "POINCONNES" at 20.043,99.662 h1.33
  text "BOUCHAGE METAL" at 47.143,96.277 h1.33
  text "MULTICOUCHE" at -36.857,96.027 h1.33
  text "4" at 1.656,92.299 h1.33
  text "NOMBRE DE COUCHES" at -36.857,92.027 h1.33
  text "BOUCHAGE VERNIS(TIGHTENING)" at 47.143,91.277 h1.33
  text "ZONE DEFINIE" at 47.143,86.277 h1.33
  text "BORGNE" at 76.643,86.277 h1.33
  text "TRAVERSANT" at 97.143,86.277 h1.33
  text "120um" at 6.943,86.227 h1.33
  text "CLASSE DE LA CARTE" at -36.857,86.027 h1.33
  text "1.0" at 53.431,81.556 h1.33
  text "EPAISSEUR ( mm )" at 21.643,80.777 h1.33
  text "MATERIAU REF:" at -37.183,80.655 h1.33
  text "+/- 10%" at 62.143,80.527 h1.33
  text "FR1" at -37.357,78.027 h1.33
  text "FR2" at -37.357,75.027 h1.33
  text "CEM3" at -29.357,75.027 h1.33
  text "CERTIFICATIONS REQUISES:" at 22.283,73.087 h1.33
  text "CEM1" at -37.357,72.027 h1.33
  text "FR4 STD" at -37.357,69.027 h1.33
  text "FR4 TG" at -37.357,66.027 h1.33
  text "VT47" at -7.357,63.427 h1.33
  text "AUTRES" at -37.357,63.027 h1.33
  text "EPAISSEUR CUIVRE FINI" at -37.857,58.777 h1.33
  text "35" at 8.143,54.027 h1.33
  text "70" at 26.143,54.027 h1.33
  text "AUTRES:" at 43.143,54.027 h1.33
  text "COUCHES EXTERNES" at -38.107,53.777 h1.33
  text "COUCHES INTERNES" at -38.107,47.527 h1.33
  text "17.5" at -6.357,47.527 h1.33
  text "35" at 8.143,47.527 h1.33
  text "70" at 26.143,47.527 h1.33
  text "AUTRES:" at 43.143,47.527 h1.33
  text "FINITION ROHS:" at -37.857,43.027 h1.33
  text "ETAIN CHIMIQUE" at -37.857,39.027 h1.33
  text "ARGENT CHIMIQUE" at 12.143,39.027 h1.33
  text "CARBONE FACE REFERENCE" at 70.143,39.027 h1.33
  text "CUIVRE PASSIVE (OSP)" at -37.857,35.527 h1.33
  text "DORURE ELECTROLYTIQUE" at 12.143,35.527 h1.33
  text "CARBONE FACE VERSO" at 70.143,35.527 h1.33
  text "HAL ETAIN" at -37.857,32.027 h1.33
  text "DORURE CONNECTEUR" at 12.143,32.027 h1.33
  text "NiAu CHIMIQUE" at -37.857,28.527 h1.33
  text "NiAu ELECTROLYTIQUE" at -37.857,25.027 h1.33
  text "PELABLE" at 42.643,19.527 h1.33
  text "REVETEMENT EPARGNE PHOTO-IMAGEABLE" at -38.357,19.277 h1.33
  text "SUR CUIVRE NU" at -38.357,15.527 h1.33
  text "FACE REFERENCE" at 42.643,15.527 h1.33
  text "SUR CUIVRE OXYDE" at -38.357,11.527 h1.33
  text "FACE VERSO" at 42.643,11.527 h1.33
  text "SUR Ni/Au" at -38.357,7.527 h1.33
  text "MARQUAGE" at -38.357,1.277 h1.33
  text "ENCRE BLANCHE" at -10.857,0.777 h1.33
  text "FACE REFERENCE" at 36.143,0.777 h1.33
  text "AUTRES" at -10.857,-3.223 h1.33
  text "FACE VERSO" at 36.143,-3.223 h1.33
  text "CARTE UNITAIRE" at 41.893,-8.973 h1.33
  text "MONTAGE FLAN" at 78.643,-8.973 h1.33
  text "EMPILAGE DES COUCHES" at -38.357,-9.223 h1.33
  text "constitution" at -38.107,-12.473 h1.33
  text "Libre" at -15.857,-12.473 h1.33
  text "48x35.2" at 59.6,-16.2 h2
  text "DIMENSION" at 40.643,-16.473 h1.33
  text "DIMENSION" at 79.643,-16.473 h1.33
  text "Impose" at -16.249,-17.908 h1.33
  text "mm" at 47.656,-19.701 h2
  text "RAINURAGE" at 79.643,-20.473 h1.33
  text "FRAISAGE" at 79.643,-24.473 h1.33
  text "SEE STACK UP  ON DRILL DRAWING  50 ohms single 0.278mm TOP" at -31.698,-33.573 h2
  text "OBSERVATIONS" at -37.857,-41.473 h1.33
  text "Nom ou logo du fabricant et date code suivi de son homologation UL face vernis soudures" at -36.357,-44.473 h1.33
  text "EXIGENCES SUPPLEMENTAIRES" at -38.107,-56.973 h1.33
  text "Cette spécification n est qu a titre indicatif," at -34.357,-60.473 h1.33
  text "le fabricant devra se conformer uniquement a la commande du client." at -34.607,-64.473 h1.33
  text "Celle ci fera foi quant aux materiaux et finitions du CI" at -34.357,-68.473 h1.33
  text "L EMBALLAGE POUR LA LIVRAISON SERA SUFFISANT POUR ASSURER" at 13.143,-82.473 h1.33
  text "CONTRAINTES GENERALES" at -37.542,-82.623 h1.33
  text "UN TRANSPORT SANS DETERIORATION DES PRODUITS." at 13.643,-85.973 h1.33
  text "CONDITIONNEMENT" at -33.597,-86.298 h1.33
cartouche top:
  drawing of 26376 lines, arcs and shapes, not listed
  text "TOLERANCES GENERALES" at -56.107,-107.973 h1.05
  text "EN MM" at -45.169,-109.785 h1.05
  text "+" at -39.107,-111.723 h0.89
  text "20:" at -42.357,-111.848 h0.89
  text "0.1" at -37.857,-111.848 h0.89
  text "DIMENSIONS:" at -55.982,-112.098 h0.89
  text "-" at -39.107,-112.223 h0.89
  text "+" at -34.857,-114.098 h0.89
  text "0.2" at -33.607,-114.223 h0.89
  text "20-100:" at -42.357,-114.348 h0.89
  text "-" at -34.857,-114.598 h0.89
  text "+" at -33.607,-116.723 h0.89
  text "100-250:" at -42.482,-116.848 h0.89
  text "0.3" at -32.357,-116.848 h0.89
  text "-" at -33.607,-117.223 h0.89
  text "+" at -38.232,-119.223 h0.89
  text "0.4" at -36.982,-119.223 h0.89
  text "250:" at -42.357,-119.348 h0.89
  text "CREATION" at 39.543,-119.423 h1.05
  text "V1" at -19.707,-119.498 h1.05
  text "29/11/23" at 117.043,-119.673 h1.05
  text "-" at -38.232,-119.723 h0.89
  text "30°" at -46.357,-121.598 h0.89
  text "+" at -47.607,-121.723 h0.89
  text "ANGLES:" at -55.982,-121.848 h0.89
  text "-" at -47.607,-122.223 h0.89
  text "IND" at -20.857,-122.723 h1.05
  text "MODIFICATIONS" at 37.893,-122.723 h1.05
  text "DATE" at 118.893,-122.723 h1.05
  text "RESPONSABLE PROJET" at 110.865,-127.218 h1.05
  text "1/1" at -42.994,-127.498 h1.05
  text "ECHELLE:" at -54.607,-127.723 h1.05
  text "DATE:" at -54.489,-130.52 h1.05
  text "29/11/2023" at -46.418,-130.748 h1.05
  text "AQ-TECH" at 116.053,-133.258 h1.33
  text "M.MOSER" at 116.053,-136.518 h1.33
  text "STL-PCB-MAIN" at 31.143,-139.223 h2.5
  text "CE DOCUMENT NE PEUT" at 110.449,-141.596 h1.05
  text "ETRE REPRODUIT SANS" at 110.699,-143.596 h1.05
  text "OPERATEUR CAO" at -50.552,-144.998 h1.33
  text "NOTRE AUTORISATION" at 111.699,-145.596 h1.05
  text "1 1" at 93.593,-146.903 h1.33
  text "FOLIO  /" at 85.643,-146.973 h1.33
  text "JYves ROUX" at -46.728,-147.638 h1.33
  text "(LOI DU 11 MARS 1957)" at 110.449,-147.846 h1.05
cartouche bot:
  drawing of 26376 lines, arcs and shapes, not listed
  text "TOLERANCES GENERALES" at 136.393,-107.973 h1.05
  text "EN MM" at 125.456,-109.785 h1.05
  text "+" at 119.393,-111.723 h0.89
  text "0.1" at 118.143,-111.848 h0.89
  text "20:" at 122.643,-111.848 h0.89
  text "DIMENSIONS:" at 136.268,-112.098 h0.89
  text "-" at 119.393,-112.223 h0.89
  text "V3" at 100.326,-113.275 h1.05
  text "+" at 115.143,-114.098 h0.89
  text "0.2" at 113.893,-114.223 h0.89
  text "20-100:" at 122.643,-114.348 h0.89
  text "-" at 115.143,-114.598 h0.89
  text "V2" at 100.226,-116.175 h1.05
  text "+" at 113.893,-116.723 h0.89
  text "0.3" at 112.643,-116.848 h0.89
  text "100-250:" at 122.768,-116.848 h0.89
  text "-" at 113.893,-117.223 h0.89
  text "0.4" at 117.268,-119.223 h0.89
  text "+" at 118.518,-119.223 h0.89
  text "250:" at 122.643,-119.348 h0.89
  text "29/11/23" at -36.557,-119.373 h1.05
  text "CREATION" at 38.079,-119.498 h1.05
  text "V1" at 99.993,-119.498 h1.05
  text "-" at 118.518,-119.723 h0.89
  text "30°" at 126.643,-121.598 h0.89
  text "+" at 127.893,-121.723 h0.89
  text "ANGLES:" at 136.268,-121.848 h0.89
  text "-" at 127.893,-122.223 h0.89
  text "DATE" at -38.607,-122.723 h1.05
  text "MODIFICATIONS" at 42.393,-122.723 h1.05
  text "IND" at 101.143,-122.723 h1.05
  text "RESPONSABLE PROJET" at -30.579,-127.218 h1.05
  text "1/1" at 123.28,-127.498 h1.05
  text "ECHELLE:" at 134.893,-127.723 h1.05
  text "DATE:" at 134.775,-130.52 h1.05
  text "24/11/2023" at 126.704,-130.748 h1.05
  text "AQ-TECH" at -35.767,-133.258 h1.33
  text "M.MOSER" at -35.767,-136.518 h1.33
  text "STL-PCB-MAIN" at 50.643,-139.223 h2.5
  text "CE DOCUMENT NE PEUT" at -30.163,-141.596 h1.05
  text "ETRE REPRODUIT SANS" at -30.413,-143.596 h1.05
  text "OPERATEUR CAO" at 130.838,-144.998 h1.33
  text "NOTRE AUTORISATION" at -31.413,-145.596 h1.05
  text "1 1" at -13.307,-146.903 h1.33
  text "FOLIO  /" at -5.357,-146.973 h1.33
  text "JYves ROUX" at 127.014,-147.638 h1.33
  text "(LOI DU 11 MARS 1957)" at -30.163,-147.846 h1.05

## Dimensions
-0.4,-49.825 to 13.16,-21.5 on Drill Drawing
-0.4,-49.825 to 13.16,-21.5 on Drill Drawing
47.6,-45.738 to 47.596,-18.561 on Drill Drawing
-0.4,-49.825 to 47.6,-45.738 on Drill Drawing
-0.4,-49.825 to -0.4,-14.625 on Drill Drawing
-0.4,-49.825 to 47.6,-45.738 on Drill Drawing
-0.4,-49.825 to 35.933,-49.825 on Drill Drawing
